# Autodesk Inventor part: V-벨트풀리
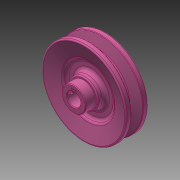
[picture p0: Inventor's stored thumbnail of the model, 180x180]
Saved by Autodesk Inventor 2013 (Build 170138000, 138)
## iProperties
Created: 2016-08
Part Number: V-벨트풀리
Material: 알루미늄 6061
Document SubType Name: Modeling
Designer: mduedu
Density: 2.71 g/cm^3
Author: mduedu
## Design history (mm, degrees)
sketch "스케치1"
  geometry: L1 (0, 17.5)-(0, -9.5); L2 (10, 9.5)-(35, 9.5); L3 (35, 9.5)-(35, 4.825); L4 (35, 4.825)-(26, 2.074); L5 (26, 2.074)-(26, 0); L6 (0, 0)-(26, 0); L7 (0, -9.5)-(35, -9.5); L8 (35, -9.5)-(35, -4.825); L9 (35, -4.825)-(26, -2.074); L10 (26, -2.074)-(26, 0); L11 (32.3, 9.5)-(32.3, -9.5); L12 (10, 9.5)-(10, 17.5); L13 (10, 17.5)-(0, 17.5); 3 further points
  constraints: 26 end point, 7 point on line, 5 perpendicular, 3 symmetric about line, 2 parallel, 1 coincident, 1 horizontal alignment, 1 vertical
  dimensions: "d2" = 70 diameter of L8 L1; "d4" = 6.3 distance between parallel lines of L10 L11; "d5" = 2.7 distance between parallel lines of L11 L8; "d6" = 8 distance of point (32.3, -4) point (32.3, 4); "d7" = 34 deg angle of L9 L4; "d30" = 9.5 distance between parallel lines of L7 L6; "d32" = 27 distance between parallel lines of L13 L7; "d33" = 20 diameter of L12 L1
revolve "회전1" sketch "스케치1" stored, may be unused: angle "d8" = 90 deg
sketch "스케치2"
  geometry: L1 (-2, 0)-(2, 0); L2 (2, 0)-(2, 7.3); L3 (2, 7.3)-(-2, 7.3); L4 (-2, 7.3)-(-2, 0); C1 r 5.5 at (0, 0); 2 further points
  constraints: 8 end point, 2 coincident, 2 parallel, 1 centre point, 1 horizontal, 1 midpoint, 1 perpendicular
  dimensions: "d9" = 11 diameter of C1; "d11" = 4 distance of L2.end L3.end; "d34" = 12.8 dimension on C1 L3
extrude "돌출1" cut sketch "스케치2" stored distance "d13" = 10; taper "d14" = 0 deg
sketch "스케치3"
  geometry: L1 (35, 4.825)-(26, 2.074) reference; L2 (26, 2.074)-(26, -2.074) reference; L3 (0, 0)-(26, 0); L4 (35, 9.5)-(35, 4.825) reference; L5 (-35, 9.5)-(35, 9.5) reference; L6 (35, 9.5)-(21, 5.22); L7 (21, 5.22)-(21, 3); L8 (21, 3)-(12, 3); L9 (12, 3)-(12, 9.5); L10 (0, 9.5)-(0, -9.5); L11 (5.123, -9.5)-(-5.5, -9.5) reference; L12 (12, 9.5)-(35, 9.5)
  constraints: 14 end point, 3 midpoint, 2 parallel, 2 perpendicular, 2 point on line, 1 collinear, 1 horizontal
  dimensions: "d15" = 3 distance between parallel lines of L3 L8; "d17" = 42 diameter of L7 L10; "d18" = 24 diameter of L9 L10
revolve "회전2" sketch "스케치3" stored, may be unused: angle "d19" = 90 deg
fillet "모깎기1" dims "d20" = 0.5, "d21" = 1, "d22" = 1
fillet "모깎기2" dims "d23" = 3
fillet "모깎기3" dims "d24" = 3
fillet "모깎기4" dims "d25" = 3
chamfer "모따기1" distance "d26" = 0.5; stored, may be unused: second distance "d27" = 2, angle "d28" = 45 deg
fillet "모깎기5" dims "d29" = 1
node "작업 평면1"
sketch "스케치4"
  geometry: L1 (-9.5, 17.5)-(9.5, 17.5) reference; 2 further points
  constraints: 1 vertical alignment
  dimensions: "d41" = 4 distance from line of L1 point (0, 13.5)
hole "구멍1" sketch "스케치4" at (0, 13.5) diameter "d42" = 2.459; stored, may be unused: countersink angle "d46" = 90 deg, drill point angle "d48" = 118 deg; dims "d43" = 6, "d44" = 4, "d45" = 2, "d47" = 8
node "솔리드1"
mirror "대칭1"
